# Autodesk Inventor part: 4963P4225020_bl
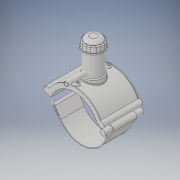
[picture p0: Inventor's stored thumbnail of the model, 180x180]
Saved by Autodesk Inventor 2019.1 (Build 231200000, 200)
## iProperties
Created: 2017-07
Part Number: 4963P4225020_bl
Material: Generic
Document SubType Name: Modeling
Designer: KIM
Density: 1 g/cm^3
Appearance: Default
Author: KIM
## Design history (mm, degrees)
derived "4963P4.ipt"
feature "Solid1::4963P4.ipt" dims "ScaleForDerivedMember" = 10
feature "Solid2::4963P4.ipt" dims "ScaleForDerivedMember" = 10
feature "Solid3::4963P4.ipt" dims "ScaleForDerivedMember" = 10
tag "TaggingFeature1"
body "Solid1"
body "Solid2"
body "Solid3"
other parameters: "d_" = 225 [user parameter], "B_" = 227 [user parameter], "L_" = 176 [user parameter], "d_t" = 6 [user parameter], "H_2" = 177 [user parameter], "H_" = 125 [user parameter], "d1" = 261 [user parameter], "d148" = 3.375 [user parameter], "d160" = 3.375 [user parameter], "d169" = 3.375 [user parameter], "d192" = 7.2 [user parameter], "d0" = 225 [user parameter], "d2" = 295.1 [user parameter], "d3" = 56.25 [user parameter], "d4" = 176 [user parameter], "d5" = 0 [user parameter], "d6" = 0.1 [user parameter], "d8" = 0 [user parameter], "d19" = 6 [user parameter], "d20" = 6 [user parameter], "d21" = 105.6 [user parameter], "d23" = 0 [user parameter], "d24" = 52.8 [user parameter], "d26" = 0 [user parameter], "d27" = 3 [user parameter], "d28" = 3 [user parameter], "d29" = 3 [user parameter], "d30" = 75 [user parameter], "d31" = 6 [user parameter], "d32" = 0 [user parameter], "d33" = 0 [user parameter], "d34" = 0.6 [user parameter], "d40" = 135.72 [user parameter], "d43" = 0 [user parameter], "d45" = 0 [user parameter], "d47" = 236.1 [user parameter], "d70" = 15 [user parameter], "d72" = 0 [user parameter], "d73" = 6 [user parameter], "d75" = 5 [user parameter], "d76" = 0 [user parameter], "d77" = 11.25 [user parameter], "d78" = 142.5 [user parameter], "d79" = 15 [user parameter], "d80" = 70.4 [user parameter], "d82" = 5 deg [user parameter], "d84" = 4 [user parameter], "d85" = 14 [user parameter], "d86" = 0 [user parameter], "d87" = 3 [user parameter], "d88" = 0 [user parameter], "d89" = 1 [user parameter], "d90" = 1 [user parameter], "d91" = 140.8 [user parameter], "d92" = 0 [user parameter], "d93" = 0.5 [user parameter], "d94" = 118.42105 [user parameter], "d96" = 266.22 [user parameter], "d97" = 3.52 [user parameter], "d98" = 0 [user parameter], "d102" = 2.25 [user parameter], "d120" = 140 deg [user parameter], "d121" = 24.228 [user parameter], "d122" = 20 deg [user parameter], "d123" = 522 [user parameter], "d124" = 156.6 [user parameter], "d126" = 0 [user parameter], "d143" = 231.75 [user parameter], "d145" = 27.69231 [user parameter], "d149" = 3.375 [user parameter], "d150" = 30.46154 [user parameter], "d153" = 176 [user parameter], "d154" = 0 [user parameter], "d156" = 130.5 [user parameter], "d157" = 160 deg [user parameter], "d159" = 7.2 [user parameter], "d161" = 3.375 [user parameter], "d162" = 105.6 [user parameter], "d163" = 0 [user parameter], "d164" = 112.5 [user parameter], "d167" = 22.5 [user parameter], "d168" = 127.31707 [user parameter], "d170" = 3.375 [user parameter], "d172" = 0 [user parameter], "d173" = 1 [user parameter], "d175" = 112.5 [user parameter], "d176" = 20 deg [user parameter], "d177" = 15.75 [user parameter], "d178" = 36 [user parameter], "d180" = 0 [user parameter], "d183" = 14.4 [user parameter], "d184" = 12.6 [user parameter], "d185" = 57.2 [user parameter], "d186" = 57.2 [user parameter], "d187" = 130.5 [user parameter], "d188" = 10.8 [user parameter], "d189" = 15.75 [user parameter], "d190" = 0 [user parameter], "d191" = 195.75 [user parameter], "d193" = 7.2 [user parameter], "d194" = 6.16 [user parameter], "d195" = 90 deg [user parameter], "d197" = 0 [user parameter], "d199" = 0 [user parameter], "d200" = 18 [user parameter], "d202" = 0 [user parameter], "d203" = 177 [user parameter], "d204" = 85.5 [user parameter], "d205" = 63 [user parameter], "d206" = 76.5 [user parameter], "d207" = 132.75 [user parameter], "d208" = 138.06 [user parameter], "d209" = 164.61 [user parameter], "d210" = 77.4 [user parameter], "d212" = 72 [user parameter], "d213" = 36 [user parameter], "d216" = 0 [user parameter], "d217" = 22.5 [user parameter], "d218" = 22.5 [user parameter], "d219" = 4.5 [user parameter]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
